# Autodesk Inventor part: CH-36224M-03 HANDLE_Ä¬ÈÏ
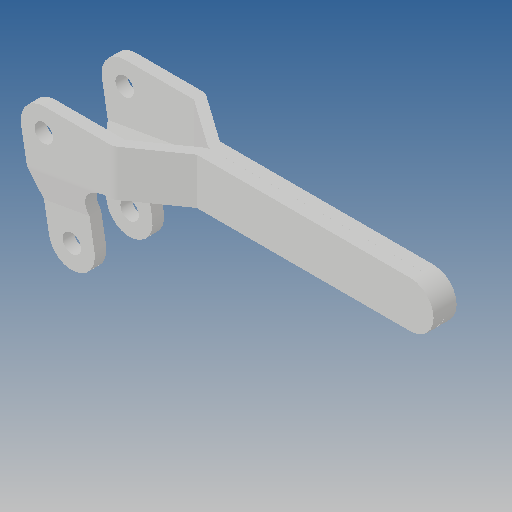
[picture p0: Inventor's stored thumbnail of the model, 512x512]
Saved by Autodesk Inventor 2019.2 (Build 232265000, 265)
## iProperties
Created: 2010-06
Part Number: CH-36224M-03 HANDLE_Ä¬ÈÏ
Material: Ogólny
Document SubType Name: Modeling
Designer: CADENGINEERING4
Density: 1 g/cm^3
Appearance: Domyślna
Author: CADENGINEERING4
Revision Number: ÈÎºÎ
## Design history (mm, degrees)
feature "NONE"
feature "NONE:1"
node "Bryła1"
node "Bryła2"
